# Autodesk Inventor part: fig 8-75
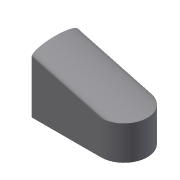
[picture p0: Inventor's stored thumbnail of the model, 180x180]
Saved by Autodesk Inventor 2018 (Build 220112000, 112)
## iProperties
Shininess: 77.0
Length Units: 11269
Angle Units: 11279
Time Units: 11290
Mass Units: 11283
Length Display Precision: 3
Angle Display Precision: 2
Created: 2002-01
Part Number: fig 8-75
Document SubType Name: Modeling
Designer: ***
Density: 1 g/cm^3
Material: Generic
Appearance: Default
Density: 0.0
Volumn: 0.0
Area: 0.0
PropertySet Name: Model Information
Control State: 0
Master: False
Checked Out: False
Author: ***
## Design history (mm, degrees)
sketch "Sketch2"
  geometry: L1 (-36.915, 19.946)-(-36.915, -14.161); L2 (-36.915, -14.161)-(13.729, -14.161); L3 (13.729, 19.946)-(-36.915, 19.946); A1 r 17.054 centre (13.729, 2.893) between (13.729, -14.161) and (13.729, 19.946)
  constraints: 6 end point, 2 point on circle, 2 tangent, 1 centre point, 1 parallel, 1 perpendicular, 1 vertical
extrude "Extrusion2" new body sketch "Sketch2" distance "d6" = 25; taper "d7" = 0 deg
feature "FaceDraft9" dims angle "d15" = 15 deg
body "Solid1"
